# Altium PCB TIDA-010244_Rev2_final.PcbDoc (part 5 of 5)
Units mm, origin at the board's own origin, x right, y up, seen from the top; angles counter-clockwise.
Board outline 155.23 x 187.6 mm, 4 copper layers (GND/Signal 1, Solid GND Layer 1, Solid Power Layer 1, GND/Signal Layer 2), stack 1.59 mm thick; 350 components, 237 nets, 1153 pads, 380 vias.
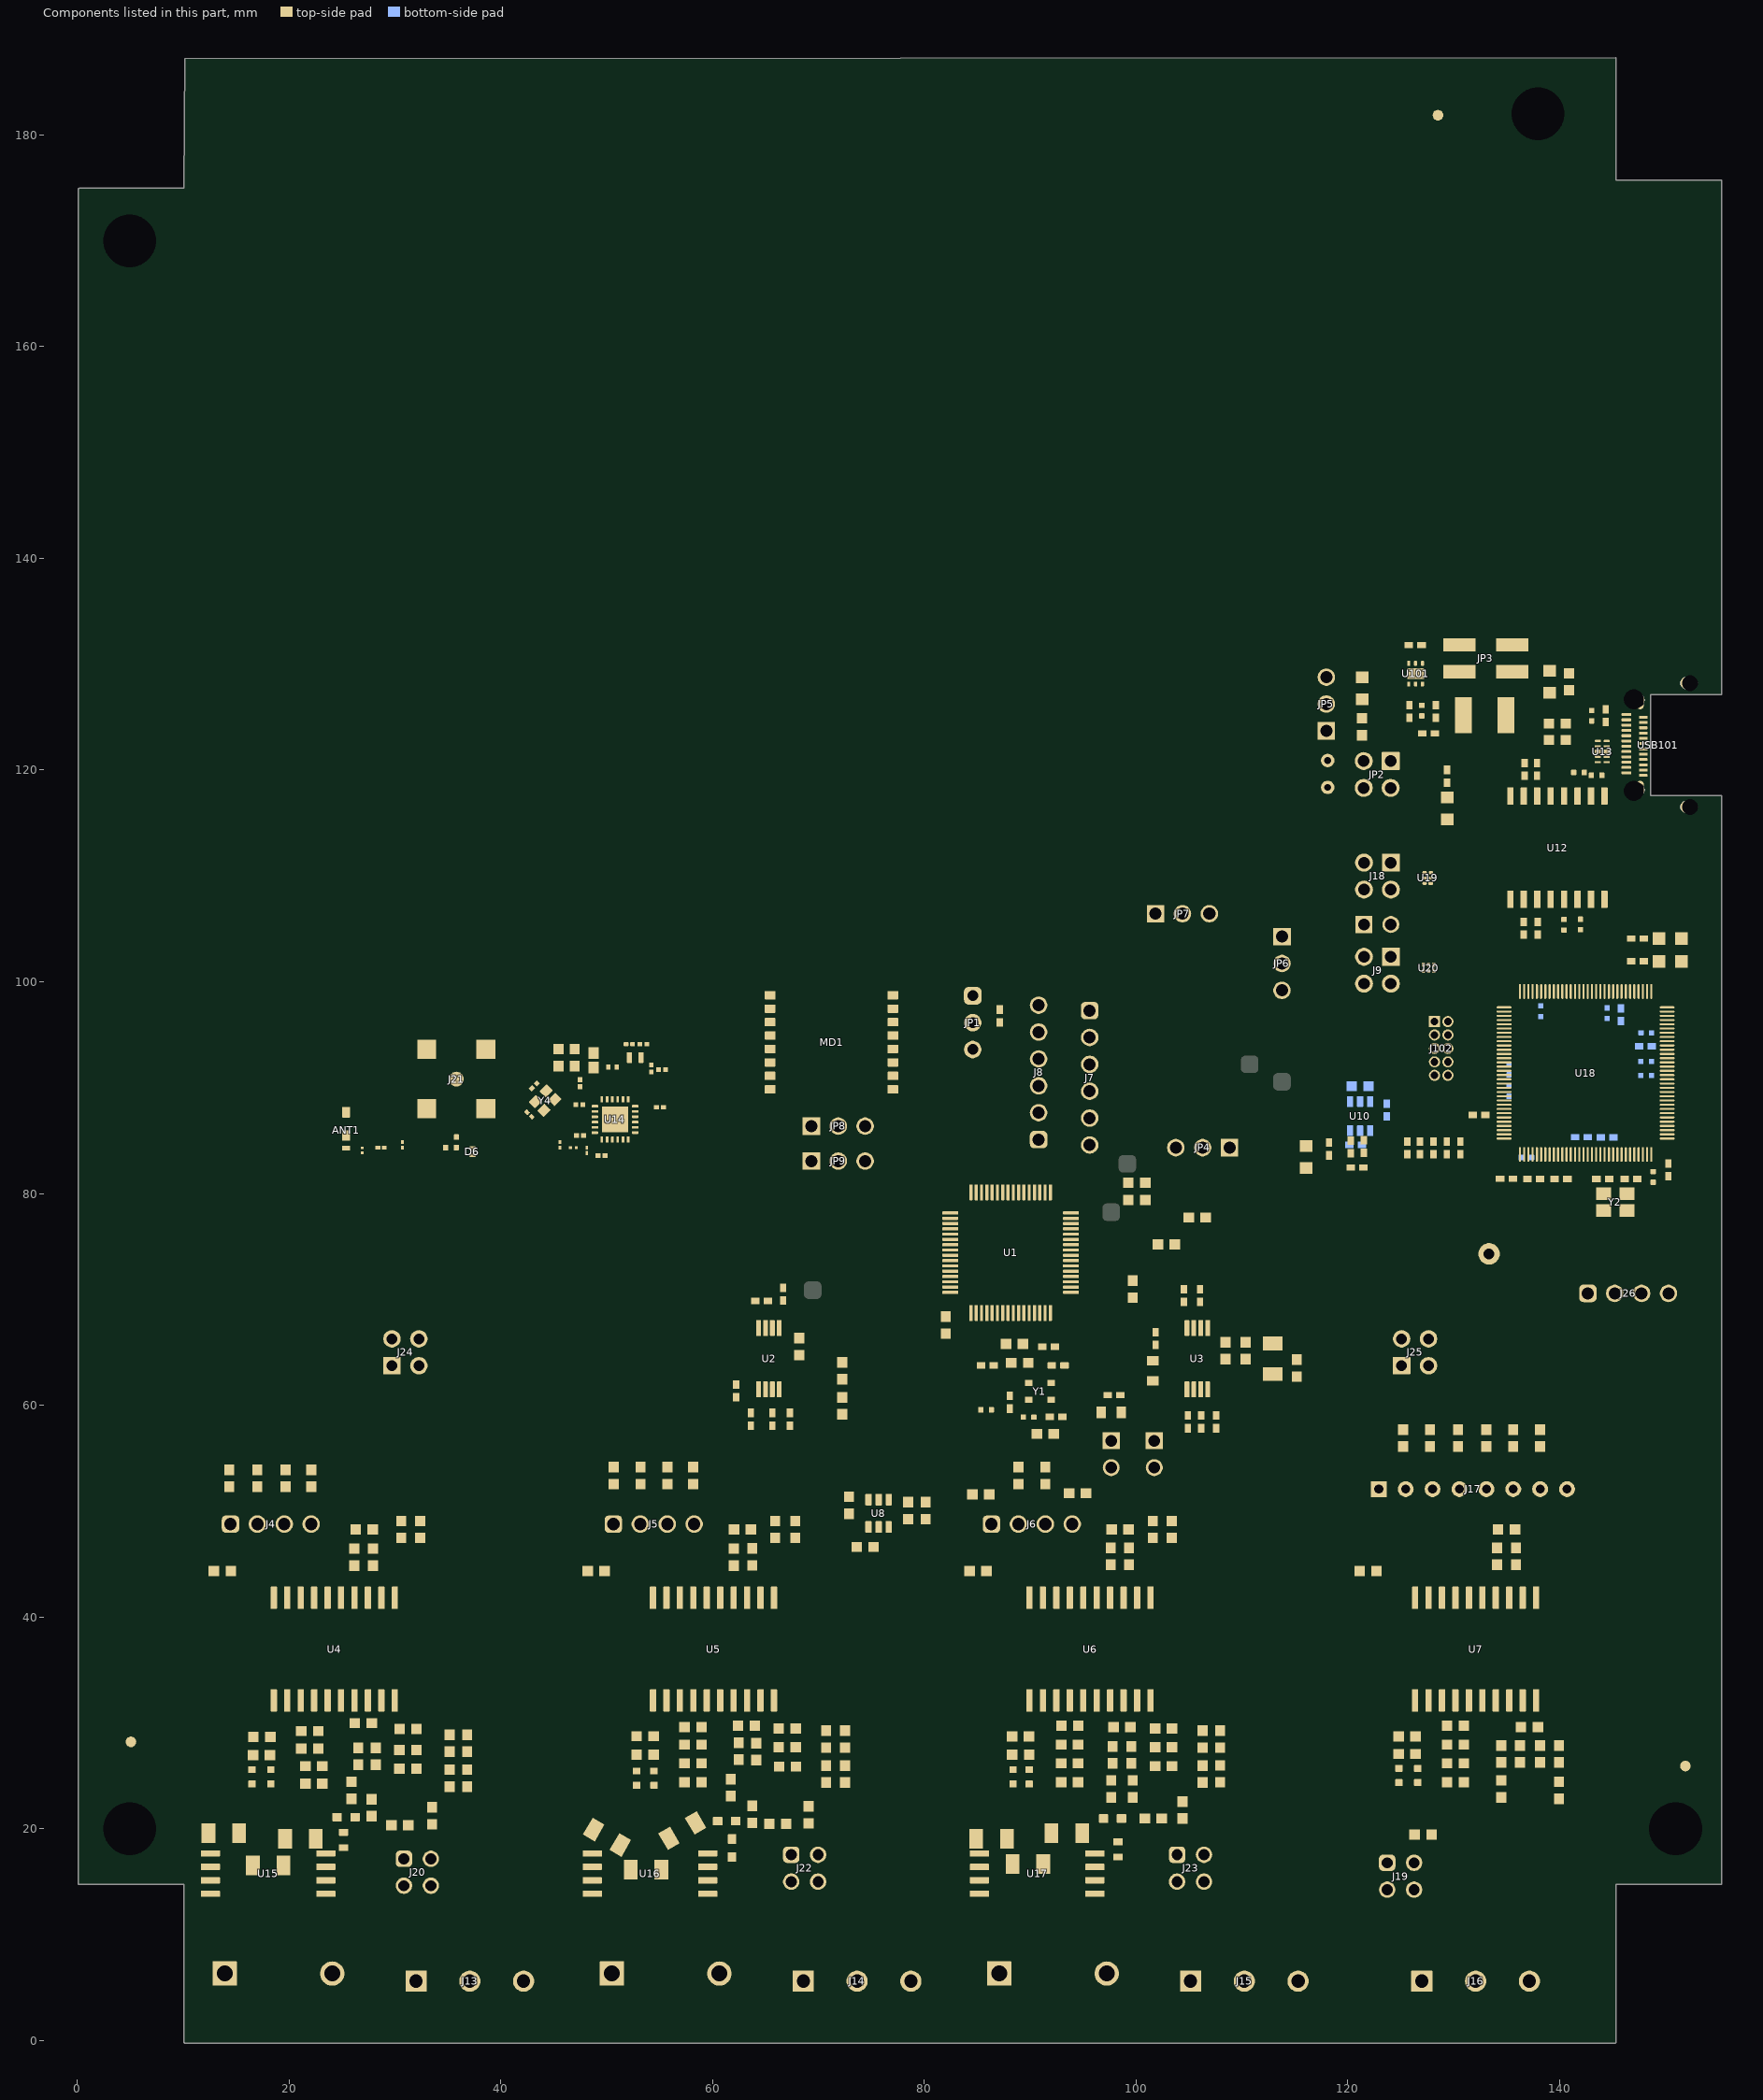
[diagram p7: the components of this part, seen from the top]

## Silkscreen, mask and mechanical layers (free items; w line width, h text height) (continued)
M16 Courtyards Bottom:
  drawing of 233 lines, arcs and shapes, not listed
  text "DESIGN INFORMATION" at 312.217,193.197 h0.76
  text "MIN. TRACK WIDTH:" at 295.845,189.841 h0.76
  text "8" at 323.69,189.841 h0.76
  text "MIL" at 327.621,189.841 h0.76
  text "7.874" at 319.464,186.75 h0.76
  text "MIN. CLEARANCE:" at 295.845,186.688 h0.76
  text "MIL" at 327.621,186.688 h0.76
  text "MIN. VIA PAD SIZE:" at 295.845,183.535 h0.76
  text "24" at 322.928,183.535 h0.76
  text "MIL" at 327.621,183.535 h0.76
  text "0.05mm (2MIL)" at 313.498,180.236 h0.76
  text "MINIMUM ANNULAR RING" at 287.483,180.027 h0.76
  text "EXTERNAL" at 331.482,180.027 h0.76
  text "PER" at 292.563,177.23 h0.76
  text "IPC-D-275 CLASS 2 LEVEL C" at 298.151,177.23 h0.76
  text "MIL, HOLES" at 335.952,174.678 h0.76
  text "+/-" at 325.984,174.459 h0.76
  text "+/-" at 347.675,174.459 h0.76
  text "REGISTRATION TOLERANCES:" at 287.483,174.432 h0.76
  text "METAL" at 317.957,174.432 h0.76
  text "5" at 332.593,174.433 h0.76
  text "3" at 353.751,174.433 h0.76
  text "MIL" at 356.704,174.432 h0.76
  text "HOLE SIZE TOLERANCE (UNLESS OTHERWISE SPECIFIED):" at 287.483,171.935 h0.76
  text "+/-" at 347.675,171.862 h0.76
  text "3" at 353.751,171.835 h0.76
  text "MIL" at 356.704,171.835 h0.76
  text "MATERIAL:" at 285.584,168.339 h0.76
  text "FR-4 High Tg" at 310.64,165.074 h0.76
  text "X" at 306.971,164.872 h0.76
  text "FR-408" at 296.277,164.757 h0.76
  text "OTHER" at 334.072,164.757 h0.76
  text "62 MIL (1.6mm) +/-10%" at 304.408,161.124 h0.76
  text "X" at 301.357,161.062 h0.76
  text "THICKNESS:" at 287.483,160.915 h0.76
  text "OTHER" at 337.044,160.915 h0.76
  text "TOLERANCE:" at 287.483,157.402 h0.76
  text "X" at 309.028,157.402 h0.76
  text "ANSI IPC-6012 TYPE 3 CLASS 2" at 313.55,157.402 h0.76
  text "OTHER +/-" at 313.549,153.739 h0.76
  text "BOW & TWIST:" at 287.483,150.052 h0.76
  text "X" at 309.028,150.052 h0.76
  text "ANSI IPC-6012 TYPE 3 CLASS 2" at 313.55,150.052 h0.76
  text "OTHER +/-" at 313.549,146.326 h0.76
  text "DRILLING:" at 285.584,143.008 h0.76
  text "NC_DRILL FILES" at 330.313,140.336 h0.76
  text "REFERENCE:" at 287.483,140.236 h0.76
  text "X" at 304.177,140.234 h0.76
  text "AS SHOWN" at 308.698,140.236 h0.76
  text "X" at 327.062,140.236 h0.76
  text "OTHER" at 337.882,136.623 h0.76
  text "PTH COPPER THICKNESS:" at 287.475,136.533 h0.76
  text "X" at 316.411,136.533 h0.76
  text "20-30 um" at 319.662,136.533 h0.76
  text "BOARD FINISH:" at 285.584,132.784 h0.76
  text "SILKSCREEN:" at 289.526,129.987 h0.76
  text "X" at 313.854,129.987 h0.76
  text "TOP" at 316.826,129.987 h0.76
  text "X" at 326.808,129.987 h0.76
  text "BOTTOM" at 329.805,129.987 h0.76
  text "SILKSCREEN COLOR:" at 289.526,126.045 h0.76
  text "X" at 313.829,126.045 h0.76
  text "WHITE" at 316.826,126.045 h0.76
  text "OTHER" at 329.805,126.045 h0.76
  text "X" at 317.156,122.402 h0.76
  text "GREEN" at 320.153,122.402 h0.76
  text "OTHER" at 335.85,122.402 h0.76
  text "SOLDER RESIST COLOR:" at 289.526,122.227 h0.76
  text "X" at 317.156,118.484 h0.76
  text "MATTE" at 320.153,118.484 h0.76
  text "SEMI-GLOSS" at 335.839,118.467 h0.76
  text "IMMERSION GOLD (ENIG)" at 312.533,114.095 h0.76
  text "ENEPIG" at 346.507,113.912 h0.76
  text "SURFACE FINISH:" at 285.584,113.886 h0.76
  text "X" at 308.012,113.886 h0.76
  text "IMM. TIN/SILVER OR EQUIV" at 293.954,110.399 h0.76
  text "OTHER" at 330.313,110.299 h0.76
  text "ARRAY/PANEL:" at 285.584,106.352 h0.76
  text "CUT AND TRIM PER M1 BOARD OUTLINE" at 312.533,106.143 h0.76
  text "N.C. ROUTE" at 312.533,102.69 h0.76
  text "X" at 330.009,102.69 h0.76
  text "V. SCORE" at 334.53,102.69 h0.76
  text "CERTIFICATION:" at 285.584,99.41 h0.76
  text "MATERIALS AND WORKMANSHIP FOR ALL PCBS" at 303.999,99.41 h0.76
  text "TO MEET OR EXCEED THE REQUIREMENTS OF:" at 303.999,97.021 h0.76
  text "X" at 294.792,93.753 h0.76
  text "ANSI IPC-A-600F CLASS ->" at 298.043,93.753 h0.76
  text "X" at 339.902,93.753 h0.76
  text "2" at 342.696,93.753 h0.76
  text "1" at 334.695,93.715 h0.76
  text "3" at 351.687,93.715 h0.76
  text "X" at 315.416,90.002 h0.76
  text "RoHS" at 318.667,90.002 h0.76
  text "OTHER" at 335.035,90.002 h0.76
  text "PER ORDER" at 345.121,90.002 h0.76
  text "ALL BOARDS MUST MEET OR EXCEED UL94-V0 REQUIREMENTS." at 286.283,86.095 h0.76
  text "PCB MUST BEAR THE UL94V-0 UL REGISTERED MATERIAL ID NUMBER" at 286.283,83.147 h0.76
  text "ADDITIONAL REQUIREMENTS:" at 285.584,78.844 h0.76
  text "MICROSECTION:" at 287.483,76.123 h0.76
  text "YES" at 310.489,76.123 h0.76
  text "REQUIRED" at 332.371,72.457 h0.76
  text "BARE BOARD ELEC. TEST:" at 287.483,72.384 h0.76
  text "NONE" at 320.649,72.384 h0.76
  text "X" at 329.374,72.384 h0.76
  text "PER ORDER" at 347.407,72.384 h0.76
  text "XX MIL VIAS REQUIRE NON-CONDUCTIVE FILL AND PLANARIZE" at 291.754,67.178 h0.76
  text "XX MIL VIAS REQUIRE CONDUCTIVE FILL AND PLANARIZE" at 291.957,64.537 h0.76
  text "OUTER XX MIL TRACES REQUIRE 50 OHM SINGLE-ENDED IMPEDANCE" at 291.932,60.387 h0.76
  text "LAYER 2 & 3 (INNER LAYERS) XX MIL WIDE, XX MIL SPACE / TRACES REQUIRE 100 OHM DIFFERENTIAL IMPEDANCE" at 291.729,54.4 h0.76
  text "ASSEMBLY VARIANT:" at 29.032,-10.77 h0.76
  text ".VariantName" at 55.347,-10.77 h0.76
  text ".VariantName" at 128.219,-10.77 h0.76
  text "ASSEMBLY VARIANT:" at 154.61,-10.77 h0.76
  text "ALL ARTWORK VIEWED FROM TOP SIDE" at -6.058,-16.4 h0.76
  text "PCB VIEWED FROM TOP SIDE" at -6.058,-16.4 h0.76
  text ".VersionControl_RevNumber" at 26.048,-16.413 h0.76
  text "SVN REV:" at 38.9,-16.413 h0.76
  text ".PCB_Rev" at 52.781,-16.413 h0.76
  text "BOARD #:" at 56.845,-16.4 h0.76
  text "BOARD #:" at 56.845,-16.4 h0.76
  text "REV:" at 60.185,-16.413 h0.76
  text ".PRJ_Number" at 70.701,-16.4 h0.76
  text ".PRJ_Number" at 70.701,-16.4 h0.76
  text ".PRJ_Number" at 81.636,-16.413 h0.76
  text "REV:" at 92.151,-16.4 h0.76
  text "REV:" at 92.151,-16.4 h0.76
  text "BOARD #:" at 95.491,-16.413 h0.76
  text ".PCB_Rev" at 99.555,-16.4 h0.76
  text ".PCB_Rev" at 99.555,-16.4 h0.76
  text "SVN REV:" at 113.436,-16.4 h0.76
  text "SVN REV:" at 113.436,-16.4 h0.76
  text ".VersionControl_RevNumber" at 126.289,-16.4 h0.76
  text ".VersionControl_RevNumber" at 126.289,-16.4 h0.76
  text "PCB VIEWED FROM BOTTOM SIDE" at 158.394,-16.413 h0.76
  text "LAYER NAME =" at -6.058,-21.552 h0.76
  text ".Layer_Name" at 14.402,-21.552 h0.76
  text ".Layer_Name" at 14.402,-21.552 h0.76
  text ".Layer_Name" at 14.402,-21.552 h0.76
  text ".Layer_Name" at 14.402,-21.552 h0.76
  text ".Layer_Name" at 14.402,-21.552 h0.76
  text ".Layer_Name" at 14.402,-21.552 h0.76
  text ".Layer_Name" at 14.402,-21.552 h0.76
  text ".Layer_Name" at 14.402,-21.552 h0.76
  text ".Layer_Name" at 14.402,-21.552 h0.76
  text ".Layer_Name" at 14.402,-21.552 h0.76
  text ".Layer_Name" at 14.402,-21.552 h0.76
  text ".Layer_Name" at 14.402,-21.552 h0.76
  text ".Layer_Name" at 14.402,-21.552 h0.76
  text ".Layer_Name" at 14.402,-21.552 h0.76
  text ".Layer_Name" at 14.402,-21.552 h0.76
  text ".Layer_Name" at 14.402,-21.552 h0.76
  text ".Layer_Name" at 14.402,-21.552 h0.76
  text ".Layer_Name" at 14.402,-21.552 h0.76
  text ".Layer_Name" at 14.402,-21.552 h0.76
  text ".Layer_Name" at 14.402,-21.552 h0.76
  text ".Layer_Name" at 14.402,-21.552 h0.76
  text ".Layer_Name" at 14.402,-21.552 h0.76
  text ".Layer_Name" at 14.402,-21.552 h0.76
  text ".Layer_Name" at 14.402,-21.552 h0.76
  text ".Layer_Name" at 14.402,-21.552 h0.76
  text "TID #:" at 56.845,-21.565 h0.76
  text "TID #:" at 56.845,-21.565 h0.76
  text ".TID" at 70.701,-21.565 h0.76
  text ".TID" at 70.701,-21.565 h0.76
  text ".TID" at 81.636,-21.577 h0.76
  text "TID #:" at 95.491,-21.577 h0.76
  text "PLOT NAME =" at -6.058,-26.78 h0.76
  text "PLOT NAME =" at -6.058,-26.78 h0.76
  text ".plot_File_Name" at 14.402,-26.78 h0.76
  text ".plot_File_Name" at 14.402,-26.78 h0.76
  text "GENERATED    :" at 56.896,-26.78 h0.76
  text "GENERATED    :" at 56.896,-26.78 h0.76
  text ".Print_Date" at 78.981,-26.78 h0.76
  text ".Print_Date" at 78.981,-26.78 h0.76
  text ".Print_Time" at 97.498,-26.78 h0.76
  text ".Print_Time" at 97.498,-26.78 h0.76
  text "TEXAS INSTRUMENTS" at 129.616,-26.78 h0.76
  text "TEXAS INSTRUMENTS" at 129.616,-26.78 h0.76
  text "TEXAS INSTRUMENTS" at 22.72,-26.793 h0.76
  text ".Print_Time" at 54.839,-26.793 h0.76
  text ".Print_Date" at 73.355,-26.793 h0.76
  text "GENERATED    :" at 95.441,-26.793 h0.76
  text ".plot_File_Name" at 137.935,-26.793 h0.76
  text "PLOT NAME =" at 158.394,-26.793 h0.76
  text "3" at 145.157,-31.839 h0.76

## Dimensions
-0.254,-9.906 to 25.146,-9.906 on M16 Courtyards Bottom
-0.254,0.254 to 0.091,14.839 on M2 Board Dimensions
-0.254,0.254 to 10.091,14.712 on M2 Board Dimensions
